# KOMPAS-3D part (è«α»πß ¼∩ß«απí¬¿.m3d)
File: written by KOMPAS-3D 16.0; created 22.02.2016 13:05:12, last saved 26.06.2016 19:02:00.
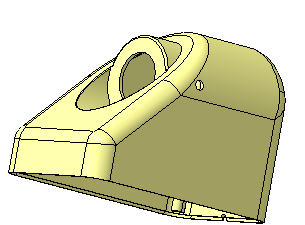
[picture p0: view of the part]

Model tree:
1. Эскиз:1
2. Операция выдавливания:1
     Расстояние 1 = 167.5
3. Эскиз:2
4. Вырезать элемент выдавливания:1
     Расстояние 1 = 250
5. Скругление:1
     Радиус = 15
6. Скругление:2
     Радиус = 15
7. Эскиз:5
8. Сечение по эскизу:3
9. Скругление:3
     Радиус = 17
10. Смещенная плоскость:2
     Расстояние = 100
11. Эскиз:7
12. Вырезать элемент выдавливания:2
     Расстояние 2 = 130; Расстояние 1 = 250
13. Операция выдавливания:2
     Расстояние 1 = 55
14. Оболочка:2
     Толщина стенки 2 = 3.5
15. Эскиз:8
16. Вырезать элемент выдавливания:3
     Расстояние 2 = 13; Расстояние 1 = 3
17. Эскиз:9
18. Вырезать элемент выдавливания:4
     Расстояние 2 = 13; Расстояние 1 = 73
19. Скругление:4
     Радиус = 4
20. Скругление:5
     Радиус = 3
21. Скругление:6
     Радиус = 2
22. Смещенная плоскость:3
     Расстояние = 72
23. Эскиз:10
24. Вырезать элемент выдавливания:5
     Расстояние 2 = 23; Расстояние 1 = 73
25. Скругление:9
     Радиус = 1
26. Смещенная плоскость:4
     Расстояние = 163
27. Эскиз:11
28. Операция выдавливания:3
     Расстояние 1 = 38; Расстояние 2 = 163
29. Эскиз:13
30. Вырезать элемент выдавливания:9
     Расстояние 1 = 40
31. Эскиз:14
32. Вырезать элемент выдавливания:10
     Расстояние 1 = 10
